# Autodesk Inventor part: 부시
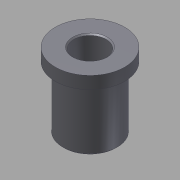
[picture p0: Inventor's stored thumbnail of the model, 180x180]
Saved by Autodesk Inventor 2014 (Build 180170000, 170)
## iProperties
Company: 한국ATC센터
Created: 2015-11
Part Number: 부시
Document SubType Name: Modeling
Designer: mdu
Density: 7.86 g/cm^3
Material: 강철, 연강
Mass: 67.4477 g
Surface Area: 43.1512 cm^2
Volume: 8.58113 cm^3
Appearance: 강철
Author: mdu
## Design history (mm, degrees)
sketch "스케치1"
  geometry: C1 r 11 at (0, 0) reference; C2 r 14 at (0, 0) reference; C3 r 11 at (0, 0) reference; 1 further point
  node "참조1"
  node "참조2"
extrude "돌출1" new body sketch "스케치1" distance "d0" = 5; taper "d1" = 0 deg
extrude "돌출2" join sketch "스케치1" distance "d2" = 25; taper "d3" = 0 deg
hole "구멍1" diameter "d6" = 13; stored, may be unused: countersink angle "d10" = 90 deg, drill point angle "d12" = 118 deg; dims "d4" = 10, "d5" = 10, "d7" = 6, "d8" = 4, "d9" = 2, "d11" = 8
chamfer "모따기1" distance "d13" = 0.5; stored, may be unused: second distance "d14" = 2, angle "d15" = 45 deg
chamfer "모따기2" distance "d16" = 0.5; stored, may be unused: second distance "d17" = 2, angle "d18" = 45 deg
node "솔리드1"
